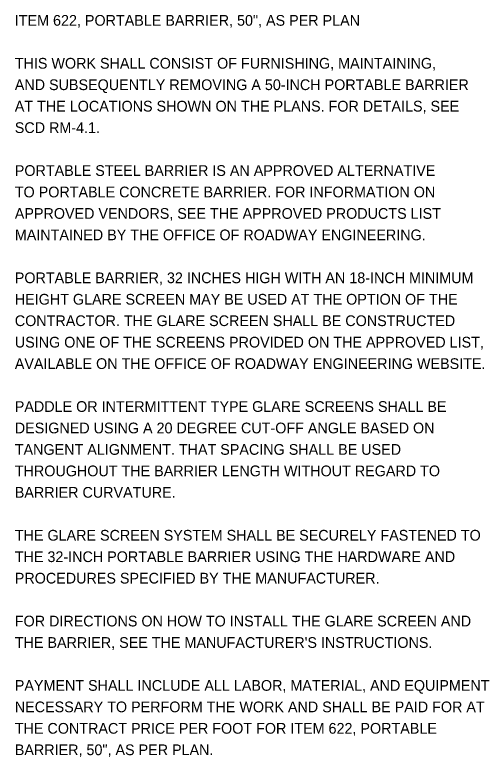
# Model space of a CAD drawing. Extents: x 0 to 47.3, y -11.1 to 22.
# Drawn here: x 20.1 to 26.3, y -11.09 to -1.41 of the extents above; entities that cross this region are included whole.
import ezdxf

# ---------------------------------------------------------------- set-up
doc = ezdxf.new("R2010")
doc.units = 0
doc.layers.add('SH_Text', color=7, linetype='Continuous')

msp = doc.modelspace()

# ---------------------------------------------------------------- texts
at = {"layer": 'SH_Text'}
for s, p in [('ITEM 622, PORTABLE BARRIER, 50", AS PER PLAN', (20.1011, -1.5474)), ('THIS WORK SHALL CONSIST OF FURNISHING, MAINTAINING,', (20.1011, -2.1074)), ('AND SUBSEQUENTLY REMOVING A 50-INCH PORTABLE BARRIER', (20.1011, -2.3874)), ('AT THE LOCATIONS SHOWN ON THE PLANS. FOR DETAILS, SEE', (20.1011, -2.6674)), ('SCD RM-4.1.', (20.1011, -2.9474)), ('PORTABLE STEEL BARRIER IS AN APPROVED ALTERNATIVE', (20.1011, -3.5074)), ('TO PORTABLE CONCRETE BARRIER. FOR INFORMATION ON', (20.1011, -3.7874)), ('APPROVED VENDORS, SEE THE APPROVED PRODUCTS LIST', (20.1011, -4.0674)), ('MAINTAINED BY THE OFFICE OF ROADWAY ENGINEERING.', (20.1011, -4.3474)), ('PORTABLE BARRIER, 32 INCHES HIGH WITH AN 18-INCH MINIMUM', (20.1011, -4.9074)), ('HEIGHT GLARE SCREEN MAY BE USED AT THE OPTION OF THE', (20.1011, -5.1874)), ('CONTRACTOR. THE GLARE SCREEN SHALL BE CONSTRUCTED', (20.1011, -5.4674)), ('USING ONE OF THE SCREENS PROVIDED ON THE APPROVED LIST,', (20.1011, -5.7474)), ('AVAILABLE ON THE OFFICE OF ROADWAY ENGINEERING WEBSITE.', (20.1011, -6.0274)), ('PADDLE OR INTERMITTENT TYPE GLARE SCREENS SHALL BE', (20.1011, -6.5874)), ('DESIGNED USING A 20 DEGREE CUT-OFF ANGLE BASED ON', (20.1011, -6.8674)), ('TANGENT ALIGNMENT. THAT SPACING SHALL BE USED', (20.1011, -7.1474)), ('THROUGHOUT THE BARRIER LENGTH WITHOUT REGARD TO', (20.1011, -7.4274)), ('BARRIER CURVATURE.', (20.1011, -7.7074)), ('THE GLARE SCREEN SYSTEM SHALL BE SECURELY FASTENED TO', (20.1011, -8.2674)), ('THE 32-INCH PORTABLE BARRIER USING THE HARDWARE AND', (20.1011, -8.5474)), ('PROCEDURES SPECIFIED BY THE MANUFACTURER.', (20.1011, -8.8274)), ('FOR DIRECTIONS ON HOW TO INSTALL THE GLARE SCREEN AND', (20.1011, -9.3874)), ("THE BARRIER, SEE THE MANUFACTURER'S INSTRUCTIONS.", (20.1011, -9.6674)), ('PAYMENT SHALL INCLUDE ALL LABOR, MATERIAL, AND EQUIPMENT', (20.1011, -10.2274)), ('NECESSARY TO PERFORM THE WORK AND SHALL BE PAID FOR AT', (20.1011, -10.5074)), ('THE CONTRACT PRICE PER FOOT FOR ITEM 622, PORTABLE', (20.1011, -10.7874)), ('BARRIER, 50", AS PER PLAN.', (20.1011, -11.0674))]:
    msp.add_text(s, height=0.14, dxfattribs=at).set_placement(p)

doc.saveas('drawing.dxf')
